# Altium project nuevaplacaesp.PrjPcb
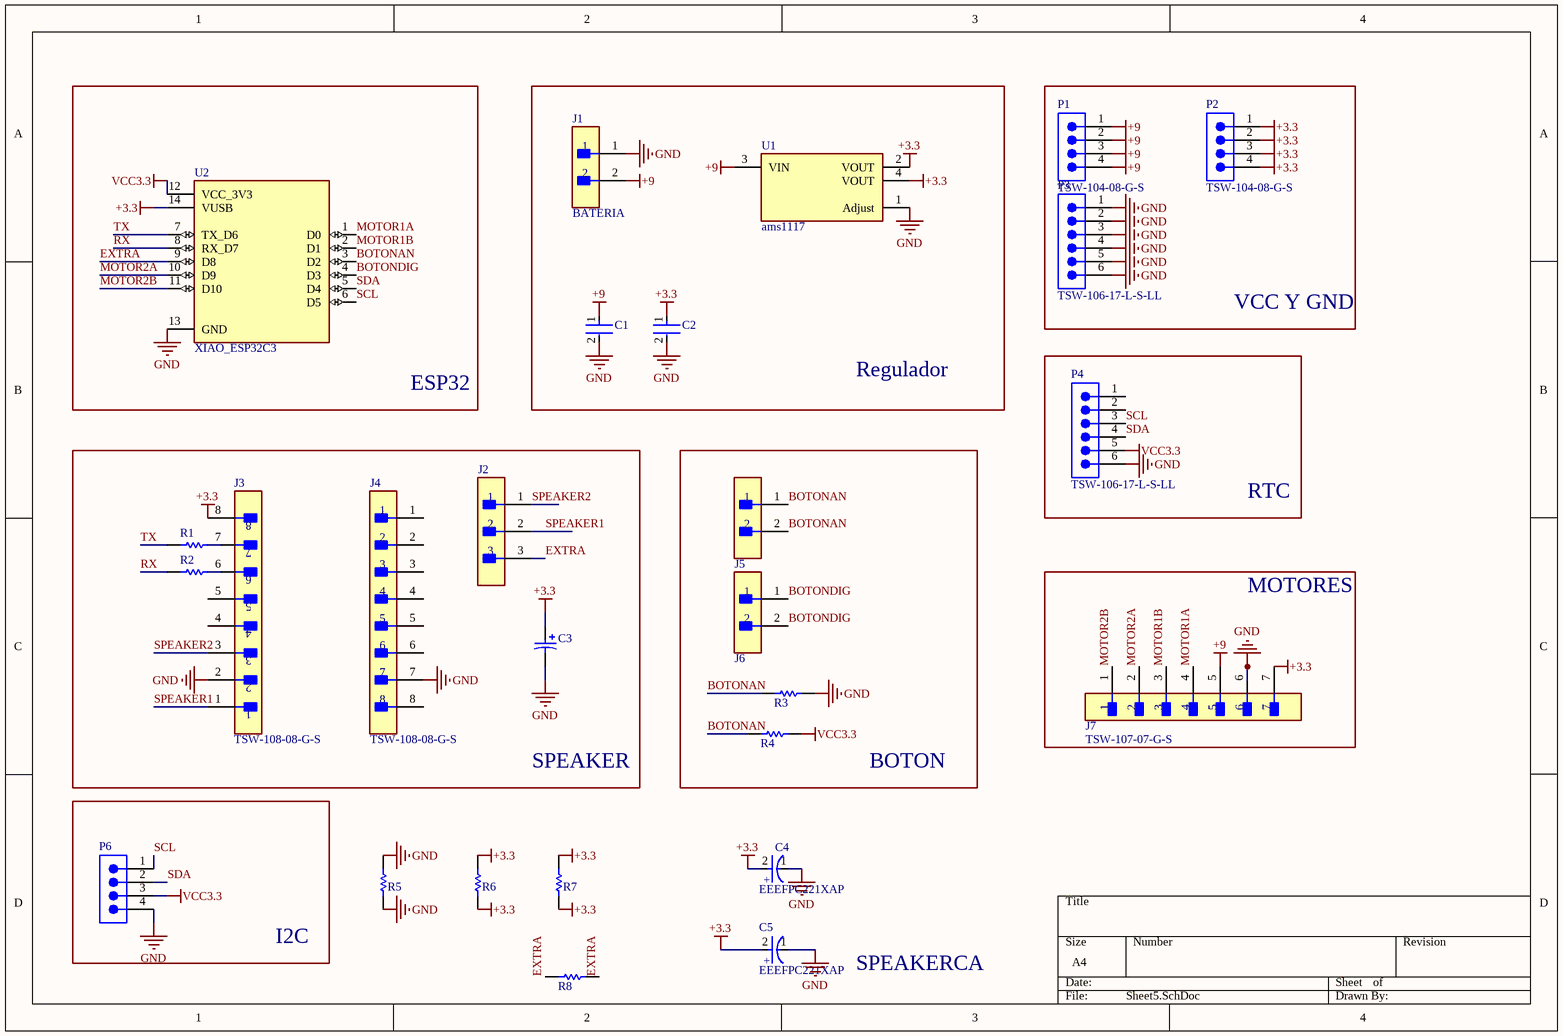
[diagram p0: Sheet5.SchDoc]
1 sheet, 27 parts. Net scope: global (net labels, ports and power ports of the same name join across sheets).
Board files: PCB5.PcbDoc, PCB2.PcbDoc

## Sheet Sheet5.SchDoc
size A4; SheetNumber: 1; SheetTotal: 1

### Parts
C1  C1206C153K5RAC  [FP-C1206C-EB-MFG]  (value not drawn)
C2  C1206C153K5RAC  [FP-C1206C-EB-MFG]  (value not drawn)
C3  50TZV100M8X10.5  [SMD-ELEC-CAP8X8]  (value not drawn)
C4  EEEFPC221XAP  [FP-FPD8-MFG]
C5  EEEFPC221XAP  [FP-FPD8-MFG]
J1  BATERIA  [FP-TSW-102-14-G-S-MFG]
J2  TSW-103-14-G-S  [FP-TSW-103-14-G-S-MFG]  (value not drawn)
J3  TSW-108-08-G-S  [FP-TSW-108-08-G-S-MFG]
J4  TSW-108-08-G-S  [FP-TSW-108-08-G-S-MFG]
J5  TSW-102-14-G-S  [FP-TSW-102-14-G-S-MFG]  (value not drawn)
J6  TSW-102-14-G-S  [FP-TSW-102-14-G-S-MFG]  (value not drawn)
J7  TSW-107-07-G-S  [FP-TSW-107-07-G-S-MFG]
P1  TSW-104-08-G-S  [SMTC-TSW-104-08-X-S]
P2  TSW-104-08-G-S  [SMTC-TSW-104-08-X-S]
P3  TSW-106-17-L-S-LL  [SMTC-TSW-106-17-X-S-LL]
P4  TSW-106-17-L-S-LL  [SMTC-TSW-106-17-X-S-LL]
P6  TSW-104-08-G-S  [SMTC-TSW-104-08-X-S]  (value not drawn)
R1  RC1206FR-10750RL  [RESC3116X65X40ML10T20]  (value not drawn)
R2  RC1206FR-10750RL  [RESC3116X65X40ML10T20]  (value not drawn)
R3  RC1206FR-076R98L  [RESC3116X65X40NL10T20]  (value not drawn)
R4  RC1206FR-076R98L  [RESC3116X65X40NL10T20]  (value not drawn)
R5  RC1206FR-076R98L  [RESC3116X65X40NL10T20]  (value not drawn)
R6  RC1206FR-076R98L  [RESC3116X65X40NL10T20]  (value not drawn)
R7  RC1206FR-076R98L  [RESC3116X65X40NL10T20]  (value not drawn)
R8  RC1206FR-076R98L  [RESC3116X65X40NL10T20]  (value not drawn)
U1  ams1117  [FP-ams1117-IPC_B]
U2  XIAO_ESP32C3  [MODULE_XIAO_ESP32C3]

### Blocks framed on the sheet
ESP32: U2
Regulador: C1 C2 J1 U1
VCC Y GND: P1-P3
RTC: P4
SPEAKER: C3 J2-J4 R1 R2
BOTON: J5 J6 R3 R4
MOTORES: J7
I2C: P6

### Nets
+3.3: C2.1 C3.A C4.2(A) C5.2(A) J3.8 J7.7 P2.1 P2.2 P2.3 P2.4 R6.1 R6.2 R7.1 R7.2 U1.2(VOUT) U1.4(VOUT) U2.14(VUSB)
+9: C1.1 J1.2 J7.5 P1.1 P1.2 P1.3 P1.4 U1.3(VIN)
GND: C1.2 C2.2 C3.C C4.1(C) C5.1(C) J1.1 J3.2 J4.7 J7.6 P3.1 P3.2 P3.3 P3.4 P3.5 P3.6 P4.6 P6.4 R3.1 R5.1 R5.2 U1.1(Adjust) U2.13(GND)
VCC3.3: P4.5 P6.3 R4.1 U2.12(VCC_3V3)
BOTONAN: J5.1 J5.2 R3.2 R4.2 U2.3(D2)
BOTONDIG: J6.1 J6.2 U2.4(D3)
EXTRA: J2.3 R8.1 R8.2 U2.9(D8)
MOTOR1A: J7.4 U2.1(D0)
MOTOR1B: J7.3 U2.2(D1)
MOTOR2A: J7.2 U2.10(D9)
MOTOR2B: J7.1 U2.11(D10)
RX: R2.1 U2.8(RX_D7)
SCL: P4.3 P6.1 U2.6(D5)
SDA: P4.4 P6.2 U2.5(D4)
SPEAKER1: J2.2 J3.1
SPEAKER2: J2.1 J3.3
TX: R1.1 U2.7(TX_D6)
NetJ3_6: J3.6 R2.2
NetJ3_7: J3.7 R1.2

Not connected (* = marked no-connect by the designer): J3 4 5; J4 1 2 3 4 5 6 8; P4 1 2

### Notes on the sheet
- SPEAKERCA

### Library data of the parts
C1 C2 = CMP-03020-027494-1: C1206 15,000 pF X7R 10.00% 50 V; Manufacturer: KEMET; Tolerance: 0.1; Voltage Rating: 50 V; Material: Ceramic; Temperature Coefficient: 15%; Automotive Grade: Grade 0
C3 = 50TZV100M8X10.5: 100 ÂµF 50 V Aluminum Electrolytic Capacitors Radial, Can - SMD - 2000 Hrs @ 105Â°C; MF: Rubycon
C4 C5 = CMP-05427-002138-1: CAP ALUM 220UF 20% 16V SMD; Life (Hours): 2000Hour; Ripple Current: 600mA; ESR (Equivalent Series Resistance): 160mR; Leakage Current: 35.2uA; Polarity: Polar; Material: Aluminium
J1 J5 J6 = CMP-02766-001740-1: CONN HEADER VERT 2POS 2.54MM; Number of Positions: 2; Max Current Rating: 7.6A; Gender: Male; Max Voltage Rating (AC): 550V
J2 = CMP-02766-001743-1: CONN HEADER VERT 3POS 2.54MM; Max Voltage Rating (AC): 550V; Number of Positions: 3; Max Current Rating: 7.6A; Gender: Male
J3 J4 = CMP-02766-000001-1: CONN HEADER VERT 8POS 2.54MM; Manufacturer: Samtec; Number Of Contacts: 8; Conn Orientation: Straight; Conn Gender: Male
J7 = CMP-02766-000065-1: CONN HEADER VERT 7POS 2.54MM; Manufacturer: SAMTEC; Conn Orientation: Straight; Number Of Contacts: 7; Conn Gender: Male
P1 P2 P6 = CMP-1024-00357-1: 0.025" SQ Post Header, Through-hole, Vertical, -55 to 125 degC, 2.54 mm Pitch, 4-Pin, Male, RoHS; Manufacturer: Samtec; Pitch: 2.54 mm
P3 P4 = CMP-1024-00394-1: 0.025" SQ Post Header, Through-hole, Vertical, -55 to 125 degC, 2.54 mm Pitch, 6-Pin, Male, RoHS; Manufacturer: Samtec; Pitch: 2.54 mm
R1 R2 = CMP-2003-04964-1: Manufacturer: Yageo
R3-R8 = CMP-2003-03854-1: Manufacturer: Yageo
U1 = CMP-209535-000002-1: 1A LOW DROPOUT VOLTAGE REGULATOR
U2 = XIAO_ESP32C3: Dev.kit: evaluation; u.FL antenna,prototype board; XIAO; PIN: 2x7; MF: Seeed Studio; MP: XIAO ESP32C3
